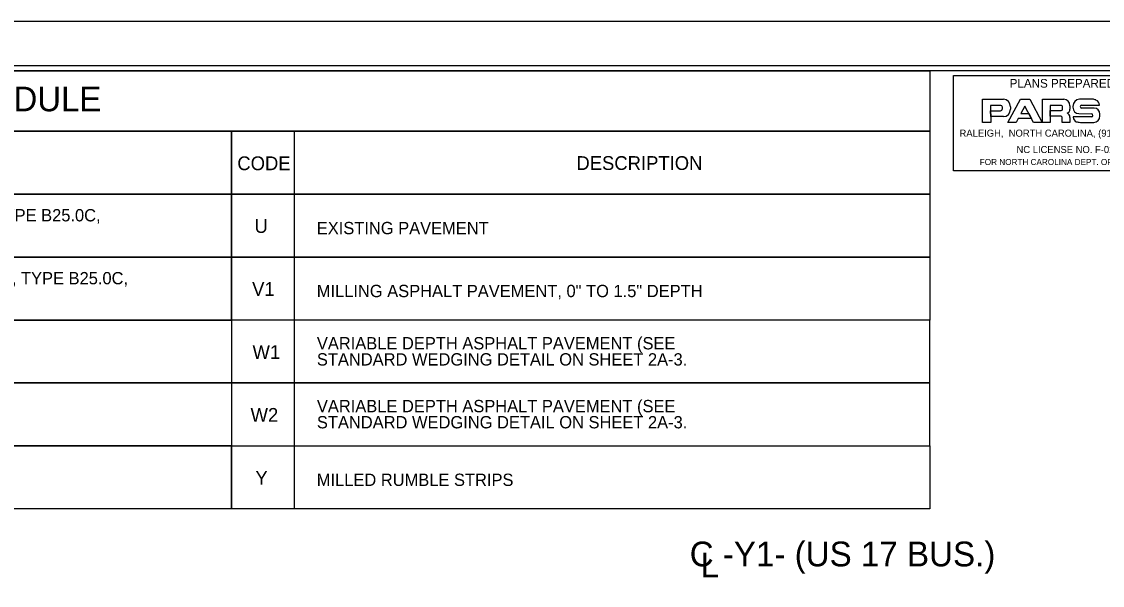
# Model space of a CAD drawing. Extents: x 2176156 to 2177167, y 76401 to 76644.
# Drawn here: x 2176765.8 to 2176853.6, y 76584.7 to 76630.5 of the extents above; entities that cross this region are included whole.
import ezdxf

# ---------------------------------------------------------------- set-up
doc = ezdxf.new("R2010")
doc.units = 0
for name, color, linetype in [('Exist Other Culture Fence Line', 7, 'Continuous'), ('Exist Other Culture Gate', 7, 'Continuous'), ('Exist Vegetation Woods Line', 7, 'Continuous'), ('Model Boundary Lines', 7, 'Continuous'), ('PH Exist DTM Breakline', 7, 'Continuous'), ('Sheet Cutting Line CELL', 7, 'Continuous'), ('Sheet Data Field CELL', 7, 'Continuous'), ('Sheet Plot Border Outside CELL', 7, 'Continuous'), ('Sheet Sticker Exception Certification CELL', 7, 'Continuous')]:
    doc.layers.add(name, color=color, linetype=linetype)

msp = doc.modelspace()

# ---------------------------------------------------------------- linework, layer by layer
at = {"layer": 'Exist Other Culture Fence Line'}
for p, q in [((2176787.984, 76601.115), (2176787.984, 76606.224)), ((2176787.986, 76596.002), (2176787.986, 76601.112))]:
    msp.add_line(p, q, dxfattribs=at)
for points in [[(2176724.542, 76616.454), (2176719.429, 76616.454), (2176719.429, 76621.568), (2176782.871, 76621.568), (2176782.871, 76616.454), (2176724.542, 76616.454), (2176724.542, 76621.568)], [(2176787.984, 76616.454), (2176782.871, 76616.454), (2176782.871, 76621.568), (2176839.615, 76621.568), (2176839.615, 76616.454), (2176787.984, 76616.454), (2176787.984, 76621.568)], [(2176724.542, 76611.339), (2176719.429, 76611.339), (2176719.429, 76616.454), (2176782.871, 76616.454), (2176782.871, 76611.339), (2176724.542, 76611.339), (2176724.542, 76616.454)], [(2176787.984, 76611.339), (2176782.871, 76611.339), (2176782.871, 76616.454), (2176839.615, 76616.454), (2176839.615, 76611.339), (2176787.984, 76611.339), (2176787.984, 76616.454)], [(2176724.542, 76606.224), (2176719.429, 76606.224), (2176719.429, 76611.339), (2176782.871, 76611.339), (2176782.871, 76606.224), (2176724.542, 76606.224), (2176724.542, 76611.339)], [(2176787.984, 76606.224), (2176782.871, 76606.224), (2176782.871, 76611.339), (2176839.615, 76611.339), (2176839.615, 76606.224), (2176787.984, 76606.224), (2176787.984, 76611.339)], [(2176724.542, 76601.11), (2176719.429, 76601.11), (2176719.429, 76606.224), (2176782.871, 76606.224), (2176782.871, 76601.11), (2176724.542, 76601.11), (2176724.542, 76606.224)], [(2176724.542, 76595.995), (2176719.429, 76595.995), (2176719.429, 76601.11), (2176782.871, 76601.11), (2176782.871, 76595.995), (2176724.542, 76595.995), (2176724.542, 76601.11)], [(2176724.542, 76590.881), (2176719.429, 76590.881), (2176719.429, 76595.995), (2176782.871, 76595.995), (2176782.871, 76590.881), (2176724.542, 76590.881), (2176724.542, 76595.995)], [(2176787.984, 76590.881), (2176782.871, 76590.881), (2176782.871, 76595.995), (2176839.615, 76595.995), (2176839.615, 76590.881), (2176787.984, 76590.881), (2176787.984, 76595.995)]]:
    msp.add_lwpolyline(points, dxfattribs=at)
for points in [[(2176782.871, 76601.114), (2176839.615, 76601.114), (2176839.615, 76606.224), (2176782.871, 76606.224)], [(2176782.872, 76596.004), (2176839.615, 76596.004), (2176839.615, 76601.114), (2176782.872, 76601.114)]]:
    msp.add_lwpolyline(points, close=True, dxfattribs=at)
at = {"layer": 'Exist Other Culture Gate'}
msp.add_lwpolyline([(2176655.987, 76626.475), (2176839.615, 76626.475), (2176839.615, 76621.568), (2176655.987, 76621.568)], close=True, dxfattribs=at)
at = {"layer": 'PH Exist DTM Breakline'}
for p, q in [((2176841.536, 76626.085), (2176863.04, 76626.085)), ((2176841.536, 76618.337), (2176841.536, 76626.085)), ((2176845.507, 76623.404), (2176845.507, 76623.514)), ((2176846.16, 76623.55), (2176846.16, 76623.367)), ((2176850.385, 76623.367), (2176850.385, 76623.575)), ((2176850.992, 76623.637), (2176850.992, 76623.354)), ((2176851.228, 76623.588), (2176851.228, 76623.513)), ((2176852.83, 76624.162), (2176851.766, 76624.162)), ((2176851.937, 76623.685), (2176853.378, 76623.685)), ((2176851.699, 76622.998), (2176852.749, 76622.976)), ((2176852.966, 76623.453), (2176851.937, 76623.453)), ((2176853.423, 76622.816), (2176853.423, 76622.963)), ((2176851.834, 76622.29), (2176852.933, 76622.29)), ((2176863.04, 76618.337), (2176841.536, 76618.337))]:
    msp.add_line(p, q, dxfattribs=at)
for points in [[(2176845.369, 76623.661), (2176844.544, 76623.661), (2176844.544, 76623.233), (2176844.555, 76622.755), (2176844.555, 76622.29), (2176843.89, 76622.29), (2176843.89, 76624.162), (2176845.587, 76624.162)], [(2176850.306, 76623.66), (2176849.379, 76623.66), (2176849.379, 76623.244), (2176849.379, 76622.791), (2176849.379, 76622.29), (2176848.762, 76622.29), (2176848.762, 76624.163), (2176850.5, 76624.163)], [(2176845.587, 76622.755), (2176844.555, 76622.755), (2176844.544, 76623.233), (2176845.347, 76623.233)], [(2176850.992, 76622.694), (2176850.992, 76622.29), (2176850.363, 76622.29), (2176850.363, 76622.719), (2176850.282, 76622.791), (2176849.379, 76622.791), (2176849.379, 76623.244), (2176850.271, 76623.244)], [(2176852.749, 76622.743), (2176851.251, 76622.743), (2176851.251, 76622.706)]]:
    msp.add_lwpolyline(points, dxfattribs=at)
msp.add_lwpolyline([(2176845.945, 76622.29), (2176846.975, 76624.162), (2176847.723, 76624.162), (2176848.742, 76622.29), (2176848.039, 76622.29), (2176847.327, 76623.6), (2176846.998, 76622.999), (2176847.655, 76622.999), (2176847.869, 76622.608), (2176846.794, 76622.608), (2176846.624, 76622.29)], close=True, dxfattribs=at)
for centre, major_axis, ratio, start_param, end_param in [((2176845.369, 76623.514), (0, 0.147), 0.93676, 4.712389, 6.283185), ((2176845.587, 76623.551), (0, 0.612), 0.93676, 4.712389, 6.283185), ((2176850.305, 76623.575), (0, 0.0857), 0.934072, 4.712389, 6.283185), ((2176850.5, 76623.636), (0, 0.526), 0.934072, 4.712389, 6.283185), ((2176851.766, 76623.587), (0, 0.575), 0.934072, 0, 1.570796), ((2176851.709, 76623.513), (0, -0.514), 0.934072, 4.712389, 6.260753), ((2176851.937, 76623.569), (0, 0.116), 0.934072, 0, 3.141593), ((2176852.829, 76623.367), (0, 0.796), 0.934072, 5.902203, 6.283185), ((2176852.944, 76623.673), (0, 0.465), 0.934072, 4.738699, 5.901866), ((2176845.347, 76623.404), (0, 0.171), 0.93676, 3.141593, 4.712389), ((2176845.587, 76623.367), (0, 0.612), 0.93676, 3.141593, 4.712389), ((2176850.271, 76623.367), (0, 0.122), 0.934072, 3.141593, 4.712389), ((2176850.694, 76623.355), (0, 0.318), 0.934072, 3.34512, 4.712389), ((2176850.648, 76622.694), (0, 0.367), 0.934072, 4.712389, 5.969561), ((2176851.606, 76622.706), (0, -0.379), 0.934072, 4.712389, 5.988639), ((2176852.749, 76622.859), (0, 0.116), 0.934072, 3.141593, 6.283185), ((2176852.932, 76622.816), (0, 0.526), 0.934072, 3.141593, 4.712389), ((2176852.966, 76622.963), (0, 0.49), 0.934072, 4.712389, 6.283185), ((2176851.834, 76623.514), (0, 1.224), 0.934072, 2.847261, 3.141593)]:
    msp.add_ellipse(centre, major_axis=major_axis, ratio=ratio, start_param=start_param, end_param=end_param, dxfattribs=at)
at = {"layer": 'Sheet Cutting Line CELL'}
msp.add_lwpolyline([(2176898.707, 76630.475), (2176629.267, 76630.475), (2176629.267, 76454.475), (2176898.707, 76454.475)], close=True, dxfattribs=at)
at = {"layer": 'Sheet Data Field CELL'}
msp.add_lwpolyline([(2176895.987, 76626.475), (2176655.987, 76626.475), (2176655.987, 76458.475), (2176895.987, 76458.475)], close=True, dxfattribs=at)
at = {"layer": 'Sheet Plot Border Outside CELL'}
msp.add_lwpolyline([(2176897.987, 76626.883), (2176631.347, 76626.883), (2176631.347, 76458.067), (2176897.987, 76458.067)], close=True, dxfattribs=at)
at = {"layer": 'Sheet Sticker Exception Certification CELL'}
msp.add_line((2176898.707, 76630.475), (2176629.267, 76630.475), dxfattribs=at)

# ---------------------------------------------------------------- texts
at = {"layer": 'Exist Other Culture Fence Line'}
for s, height, p in [('FINAL PAVEMENT SCHEDULE', 2, (2176733.957, 76623.188)), ('PROP. APPROX. 4" ASPHALT CONCRETE BASE COURSE, TYPE B25.0C,', 1, (2176726.361, 76614.242)), ('U ', 1.12, (2176784.744, 76613.302)), ('EXISTING PAVEMENT', 1, (2176789.802, 76613.199)), ('PROP. APPROX. 4 1/2" ASPHALT CONCRETE BASE COURSE, TYPE B25.0C,', 1, (2176726.361, 76609.127)), ('V1', 1.12, (2176784.549, 76608.187)), ('MILLING ASPHALT PAVEMENT, 0" TO 1.5" DEPTH', 1, (2176789.802, 76608.085)), ('W1', 1.12, (2176784.581, 76603.061)), ('VARIABLE DEPTH ASPHALT PAVEMENT (SEE ', 1, (2176789.809, 76603.839)), ('STANDARD WEDGING DETAIL ON SHEET 2A-3.', 1, (2176789.809, 76602.528)), ('VARIABLE DEPTH ASPHALT PAVEMENT (SEE ', 1, (2176789.811, 76598.732)), ('W2', 1.12, (2176784.422, 76597.954)), ('STANDARD WEDGING DETAIL ON SHEET 2A-3.', 1, (2176789.811, 76597.421)), ('Y', 1.12, (2176784.815, 76592.844)), ('MILLED RUMBLE STRIPS', 1, (2176789.802, 76592.741))]:
    msp.add_text(s, height=height, dxfattribs=at).set_placement(p)
at = {"layer": 'Exist Vegetation Woods Line'}
msp.add_text('C -Y1- (US 17 BUS.)', height=2.01314, dxfattribs=at).set_placement((2176820.098, 76586.207))
msp.add_text('L', height=2.013, rotation=359.9469, dxfattribs=at).set_placement((2176820.976, 76585.305))
at = {"layer": 'Model Boundary Lines'}
for s, p in [('CODE', (2176783.347, 76618.401)), ('DESCRIPTION', (2176810.895, 76618.421))]:
    msp.add_text(s, height=1.12, rotation=0.00002, dxfattribs=at).set_placement(p)
at = {"layer": 'PH Exist DTM Breakline'}
for s, height, rotation, p in [('PLANS PREPARED BY : ', 0.70633, 359.99904, (2176846.092, 76625.108)), ('RALEIGH,  NORTH CAROLINA, (919) 854-1345', 0.57206, 359.99996, (2176842.019, 76621.126)), ('NC LICENSE NO. F-0246', 0.57206, 359.99996, (2176846.649, 76619.794)), ('FOR NORTH CAROLINA DEPT. OF TRANSPORTATION', 0.4962, 359.99995, (2176843.663, 76618.82))]:
    msp.add_text(s, height=height, rotation=rotation, dxfattribs=at).set_placement(p)

doc.saveas('drawing.dxf')
